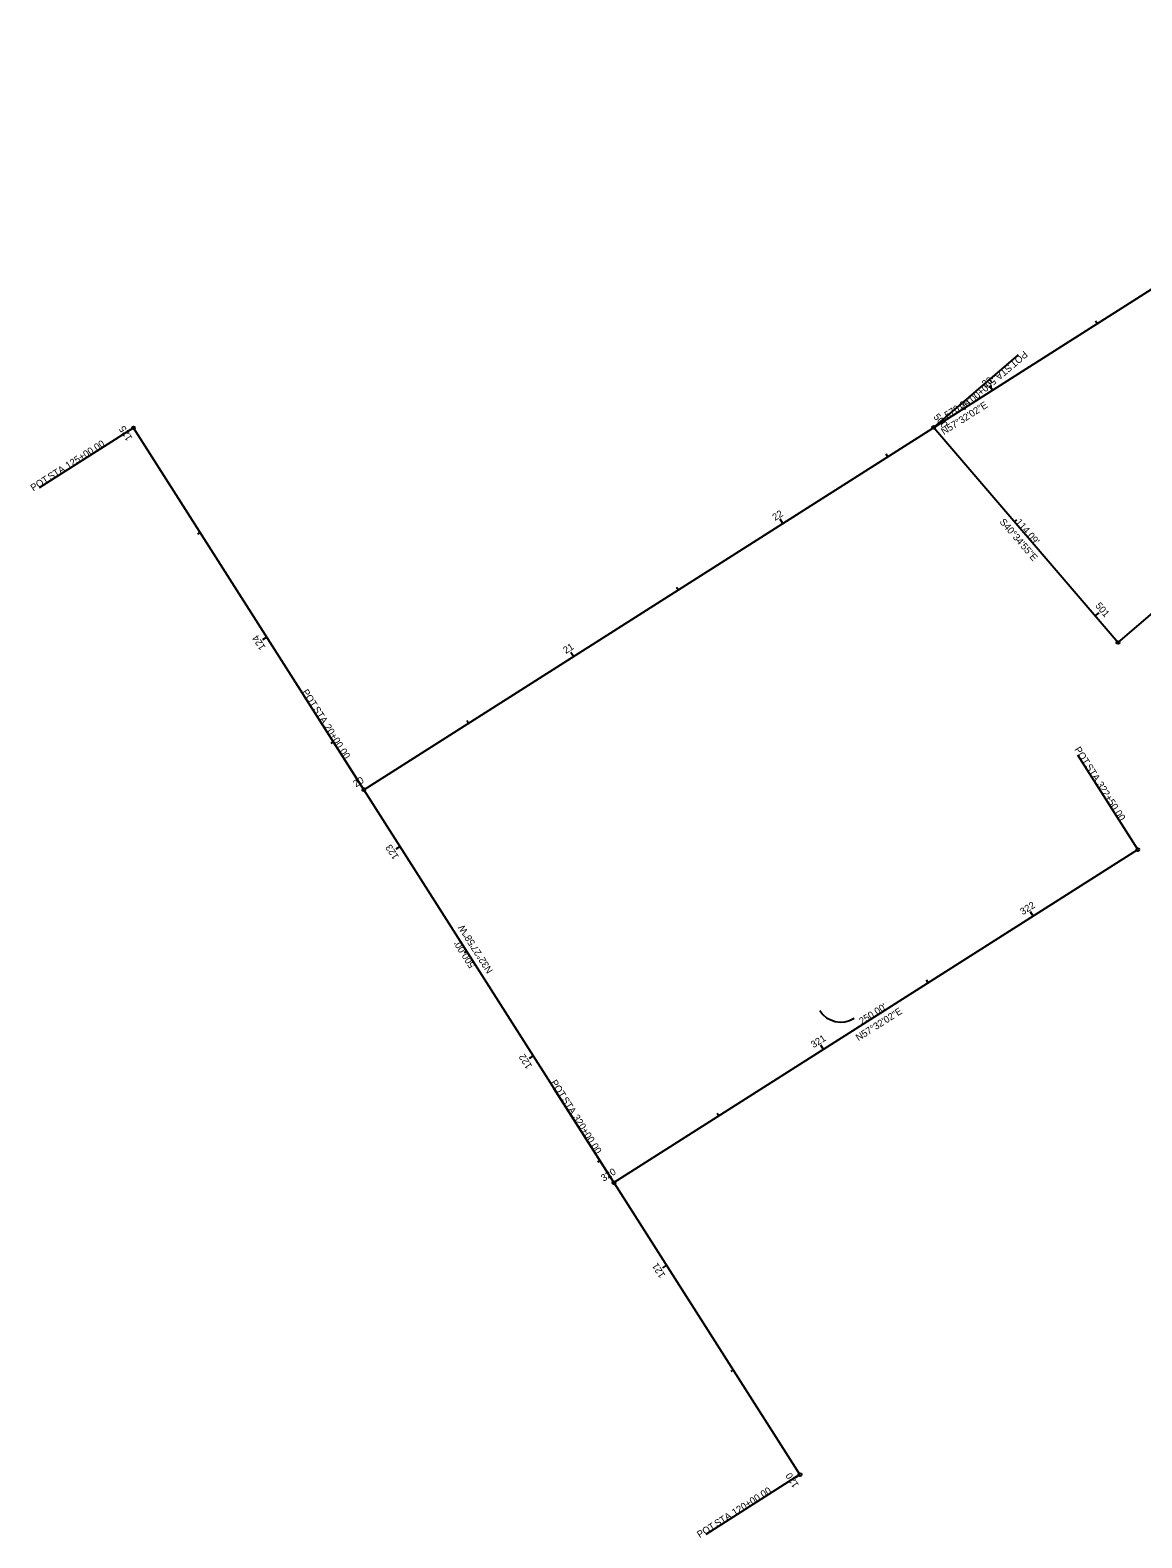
# Model space of a CAD drawing. Extents: x 144966 to 145878, y 513593 to 514347.
# Drawn here: x 144966 to 145414, y 513593 to 514200 of the extents above; entities that cross this region are included whole.
import ezdxf

# ---------------------------------------------------------------- set-up
doc = ezdxf.new("R2010")
doc.units = 0
for name, color, linetype in [('GE_P_Alignment', 7, 'Continuous'), ('GE_P_Alignment_100_Bearings', 7, 'Continuous'), ('GE_P_Alignment_100_Cardinal_Points', 7, 'Continuous'), ('GE_P_Alignment_100_Curve_Data', 7, 'Continuous'), ('GE_P_Alignment_100_Distances', 7, 'Continuous'), ('GE_P_Alignment_100_Stations', 7, 'Continuous'), ('PF_X_Ground_Line', 7, 'Continuous')]:
    doc.layers.add(name, color=color, linetype=linetype)

msp = doc.modelspace()

# ---------------------------------------------------------------- linework, layer by layer
at = {"layer": 'GE_P_Alignment'}
msp.add_arc((145292.75, 513810.73), 10, 212.46616, 302.46616, dxfattribs=at)
at = {"layer": 'GE_P_Alignment_100_Bearings'}
for p, q in [((145100.75, 513894.34), (145581.86, 514200.45)), ((145276.35, 513618.34), (145007.95, 514040.19)), ((145330.21, 514040.34), (145404.43, 513953.69)), ((145201.46, 513736.05), (145412.39, 513870.25))]:
    msp.add_line(p, q, dxfattribs=at)
at = {"layer": 'GE_P_Alignment_100_Curve_Data'}
for p, q in [((145330.21, 514040.34), (145364.39, 514069.61)), ((145007.95, 514040.19), (144969.99, 514016.04)), ((145404.43, 513953.69), (145438.61, 513982.96)), ((145100.75, 513894.34), (145076.59, 513932.31)), ((145412.39, 513870.25), (145388.23, 513908.22)), ((145201.46, 513736.05), (145177.3, 513774.02)), ((145276.35, 513618.34), (145238.39, 513594.18))]:
    msp.add_line(p, q, dxfattribs=at)
for centre in [(145007.95, 514040.19), (145330.21, 514040.34), (145404.43, 513953.69), (145100.75, 513894.34), (145412.39, 513870.25), (145201.46, 513736.05), (145276.35, 513618.34)]:
    msp.add_circle(centre, 0.6, dxfattribs=at)
at = {"layer": 'GE_P_Alignment_100_Stations'}
for p, q in [((145396.05, 514082.22), (145395.4, 514083.24)), ((145353.86, 514055.38), (145352.79, 514057.07)), ((145330.21, 514040.34), (145331.73, 514041.64)), ((145007.95, 514040.19), (145006.27, 514039.12)), ((145311.67, 514028.54), (145311.03, 514029.56)), ((145269.49, 514001.7), (145268.42, 514003.39)), ((145362.74, 514002.37), (145363.65, 514003.15)), ((145034.79, 513998.01), (145033.78, 513997.36)), ((145227.3, 513974.86), (145226.66, 513975.88)), ((145395.27, 513964.39), (145396.79, 513965.69)), ((145061.63, 513955.82), (145059.95, 513954.75)), ((145185.12, 513948.02), (145184.04, 513949.71)), ((145142.93, 513921.18), (145142.29, 513922.2)), ((145088.47, 513913.64), (145087.46, 513912.99)), ((145100.75, 513894.34), (145099.67, 513896.03)), ((145115.31, 513871.45), (145113.63, 513870.38)), ((145412.39, 513870.25), (145411.74, 513871.26)), ((145370.2, 513843.41), (145369.13, 513845.1)), ((145142.15, 513829.26), (145141.14, 513828.62)), ((145328.02, 513816.57), (145327.37, 513817.58)), ((145168.99, 513787.08), (145167.31, 513786.01)), ((145285.83, 513789.73), (145284.76, 513791.42)), ((145243.65, 513762.89), (145243, 513763.9)), ((145195.83, 513744.89), (145194.82, 513744.25)), ((145201.46, 513736.05), (145200.39, 513737.74)), ((145222.67, 513702.71), (145220.99, 513701.63)), ((145249.51, 513660.52), (145248.5, 513659.88)), ((145276.35, 513618.34), (145274.67, 513617.26))]:
    msp.add_line(p, q, dxfattribs=at)
at = {"layer": 'PF_X_Ground_Line'}
msp.add_arc((145292.75, 513810.73), 10, 212.46616, 302.46616, dxfattribs=at)

# ---------------------------------------------------------------- texts
at = {"layer": 'GE_P_Alignment_100_Cardinal_Points'}
for s, rotation, p in [('N57°32\'02"E', 32.46616, (145334.3, 514037.25)), ('S40°34\'55"E', 310.58186, (145356.56, 514002.2)), ('N32°27\'58"W', 122.46616, (145152.81, 513821.45)), ('N57°32\'02"E', 32.46616, (145299.91, 513793))]:
    msp.add_text(s, height=2.8, rotation=rotation, dxfattribs=at).set_placement(p)
at = {"layer": 'GE_P_Alignment_100_Curve_Data'}
for s, rotation, p in [('POT', 220.58186, (145366.54, 514071.4)), ('500+00.00', 220.58186, (145353.9, 514060.57)), (' STA. ', 220.58186, (145361.07, 514066.72)), ('125+00.00', 32.46616, (144981.65, 514023.51)), (' STA. ', 32.46616, (144973.68, 514018.43)), ('POT', 32.46616, (144967.6, 514014.57)), ('POT', 302.46616, (145075.72, 513933.75)), (' STA. ', 302.46616, (145079.59, 513927.68)), ('20+00.00', 302.46616, (145084.66, 513919.7)), ('POT', 302.46616, (145386.76, 513910.6)), (' STA. ', 302.46616, (145390.63, 513904.53)), ('322+50.00', 302.46616, (145395.7, 513896.55)), ('POT', 302.46616, (145175.84, 513776.4)), (' STA. ', 302.46616, (145179.7, 513770.33)), ('320+00.00', 302.46616, (145184.78, 513762.35)), ('120+00.00', 32.46616, (145250.05, 513601.65)), ('POT', 32.46616, (145236, 513592.71)), (' STA. ', 32.46616, (145242.08, 513596.58))]:
    msp.add_text(s, height=2.8, rotation=rotation, dxfattribs=at).set_placement(p)
at = {"layer": 'GE_P_Alignment_100_Distances'}
for s, rotation, p in [("570.24'", 32.46616, (145335.65, 514043.85)), ("114.09'", 310.58186, (145363.01, 514002.11)), ("500.00'", 122.46616, (145145.7, 513823.61)), ("250.00'", 32.46616, (145301.27, 513799.6))]:
    msp.add_text(s, height=2.8, rotation=rotation, dxfattribs=at).set_placement(p)
at = {"layer": 'GE_P_Alignment_100_Stations'}
for s, rotation, p in [('23', 32.46616, (145350.7, 514056.34)), ('500', 310.58186, (145329.93, 514044.51)), ('125', 122.46616, (145007.62, 514036.06)), ('22', 32.46616, (145266.32, 514002.65)), ('501', 310.58186, (145395.12, 513968.41)), ('124', 122.46616, (145061.28, 513951.72)), ('21', 32.46616, (145182.06, 513949.04)), ('20', 32.46616, (145097.52, 513895.26)), ('123', 122.46616, (145114.96, 513867.35)), ('322', 32.46616, (145366.09, 513843.76)), ('321', 32.46616, (145281.83, 513790.15)), ('122', 122.46616, (145168.65, 513782.97)), ('320', 32.46616, (145197.29, 513736.36)), ('121', 122.46616, (145222.26, 513698.71)), ('120', 122.46616, (145276.04, 513614.17))]:
    msp.add_text(s, height=2.8, rotation=rotation, dxfattribs=at).set_placement(p)

doc.saveas('drawing.dxf')
